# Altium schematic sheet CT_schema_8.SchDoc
size 413 x 333 mm
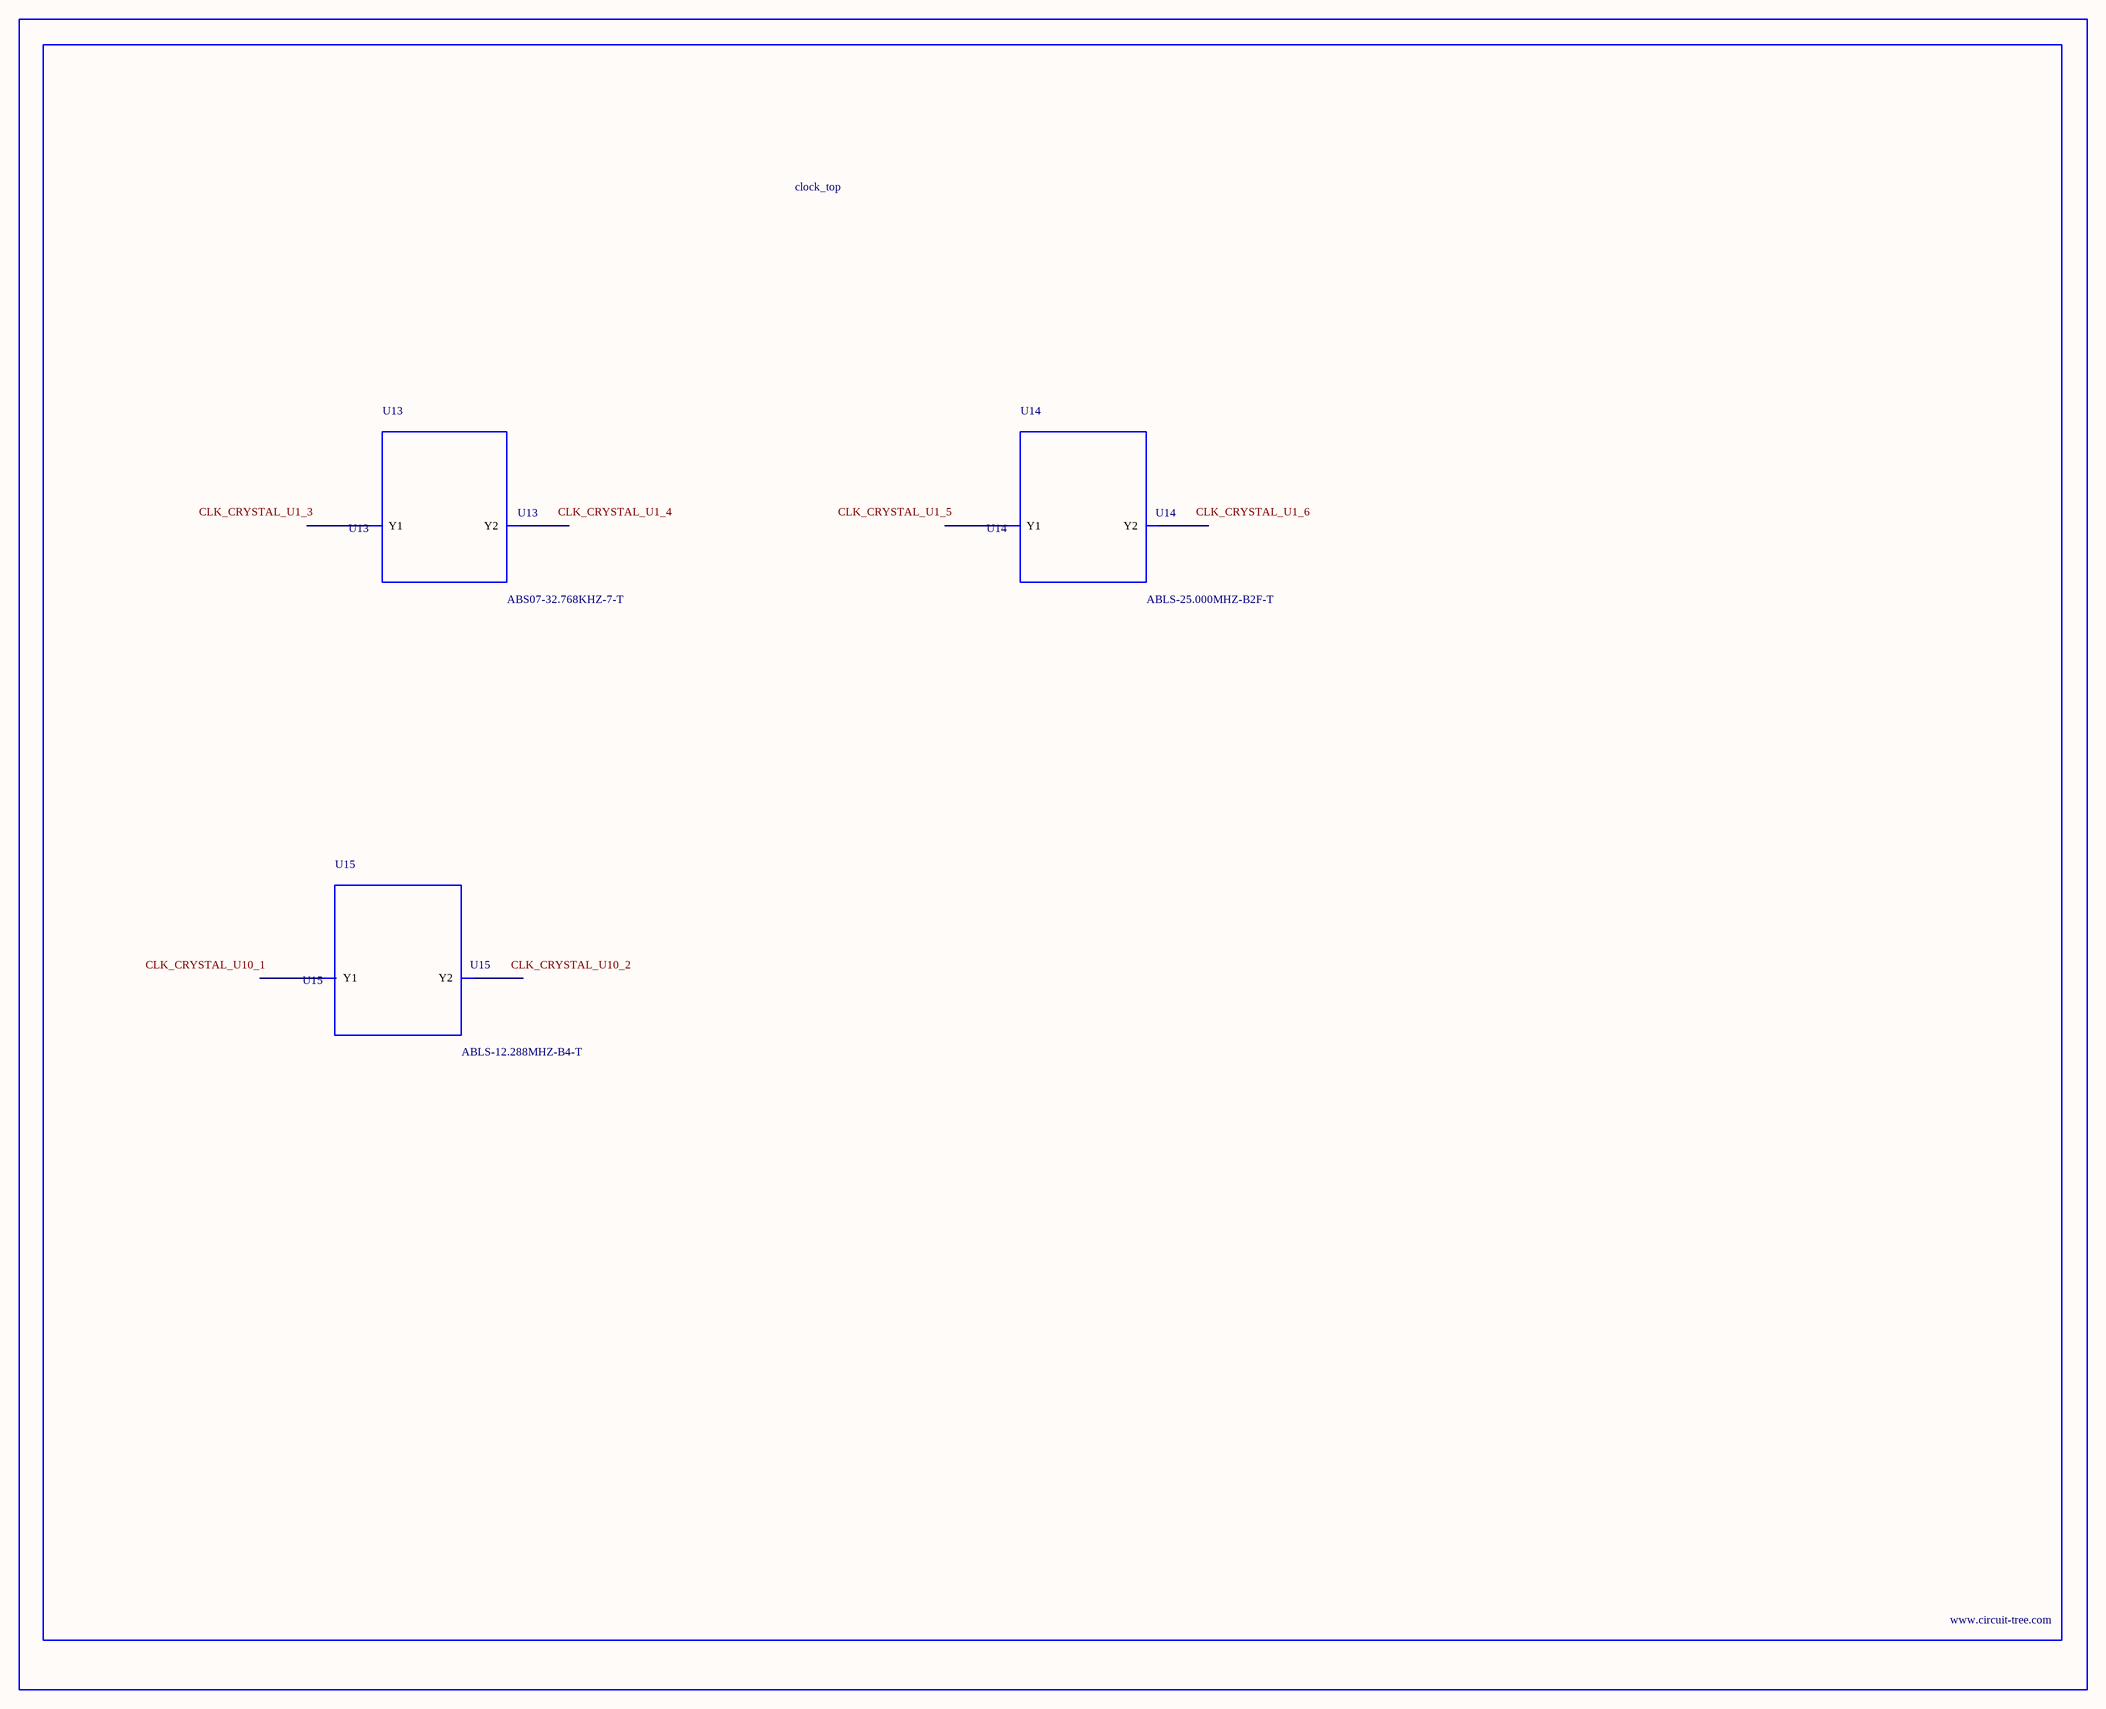
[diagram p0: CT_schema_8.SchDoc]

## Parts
BORDER7  (no value)
U13  ABS07-32.768KHZ-7-T  [ABS07-32.768KHZ-7-T]
U14  ABLS-25.000MHZ-B2F-T  [ABLS-25.000MHZ-B2F-T]
U15  ABLS-12.288MHZ-B4-T  [ABLS-12.288MHZ-B4-T]

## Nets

Not connected (* = marked no-connect by the designer): U13 1(Y1) 2(Y2); U14 1(Y1) 2(Y2); U15 1(Y1) 2(Y2)

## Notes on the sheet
- Labels drawn without touching a wire or pin: CLK_CRYSTAL_U1_3, CLK_CRYSTAL_U1_4, CLK_CRYSTAL_U1_5, CLK_CRYSTAL_U1_6, CLK_CRYSTAL_U10_1, CLK_CRYSTAL_U10_2

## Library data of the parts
BORDER7 = BORDER_PAGE7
